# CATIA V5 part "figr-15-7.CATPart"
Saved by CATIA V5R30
Part number: Part1
Bounding box of the stored display mesh (mm): x -50 to 50, y -32.5 to 33.5, z -52 to 1
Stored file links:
  D:\PROJECTS\CATIA V56R 2020\Resources\Parts File\c15_catia_v5_6r2020_prt\figr-15-7.CATPart
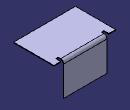
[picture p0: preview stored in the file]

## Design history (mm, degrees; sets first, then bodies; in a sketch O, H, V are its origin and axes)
SheetMetalParameters1: Thickness 1, BendRadius 4, KFactor 0.475772 {= log(min(100,max(20*SheetMetalParameters1.BendRadius,SheetMetalParameters1.Thickness)/SheetMetalParameters1.Thickness))/log(100)/2}, ReliefRadialLength 4, ReliefAxialLength 4, MinimumBendRadius 0
Body1 (main body)
  Sketch1 on xy-plane, origin (0, 0, 0), H (1, 0, 0), V (0, 1, 0)
    line L1 (-50, 32.5) -> (50, 32.5)
    line L2 (50, 32.5) -> (50, -32.5)
    line L3 (50, -32.5) -> (-50, -32.5)
    line L4 (-50, -32.5) -> (-50, 32.5)
    length L1 = 100
    length L2 = 65
    horizontal: L1 H, L3 H
    vertical: L2 V, L4 V
    symmetry: L4 L2 V, L1 L3 H
  Wall1: Thickness 1, Profile Sketch1
  d_NewWallOnEdge1: NewWallOnEdge_Edge edge [face of Wall1 | face of Wall1], NewWallOnEdge_Length 53, NewWallOnEdge_HeightLimitOffset 0, NewWallOnEdge_WidthOffset1 -15, NewWallOnEdge_WidthOffset2 -15, NewWallOnEdge_Angle 90, NewWallOnEdge_BendRadiusValue 4 {= SheetMetalParameters1.BendRadius}, NewWallOnEdge_BendTable SheetMetalParameters1, KFacteur 0.475772 {= log(min(100,max(20*d_NewWallOnEdge1.Radius,SheetMetalParameters1.Thickness)/SheetMetalParameters1.Thickness))/log(100)/2}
